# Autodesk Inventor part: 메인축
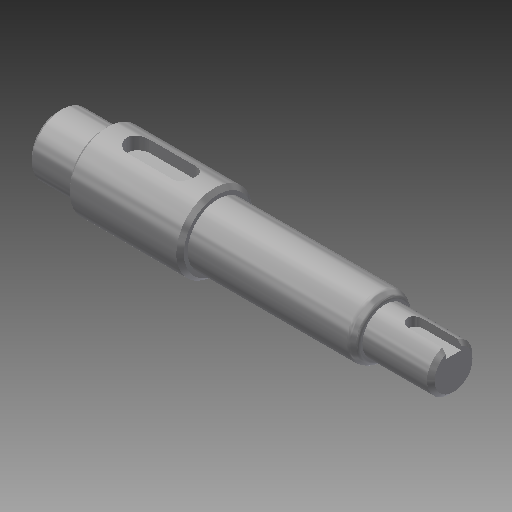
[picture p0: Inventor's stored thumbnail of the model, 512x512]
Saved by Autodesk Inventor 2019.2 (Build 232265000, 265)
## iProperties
Created: 2019-03
Part Number: 메인축
Material: 강철, 연강
Document SubType Name: Modeling
Designer: mduedu
Density: 1 g/cm^3
Appearance: 강철
Author: mduedu
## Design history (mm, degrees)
sketch "스케치1"
  geometry: L1 (0, 0)-(12, 0); L2 (12, 0)-(12, 8); L3 (12, 8)-(0, 8); L4 (0, 8)-(0, 0); L5 (12, 0)-(42, 0); L6 (42, 0)-(42, 10); L7 (42, 10)-(12, 10); L8 (12, 10)-(12, 0); L9 (42, 0)-(86, 0); L10 (86, 0)-(86, 8); L11 (86, 8)-(42, 8); L12 (42, 8)-(42, 0); L13 (86, 0)-(104, 0); L14 (104, 0)-(104, 6); L15 (104, 6)-(86, 6); L16 (86, 6)-(86, 0)
  constraints: 32 end point, 8 parallel, 4 horizontal, 4 perpendicular
  dimensions: "d0" = 16 diameter of L3 L1; "d2" = 20 diameter of L7 L5; "d3" = 16 diameter of L11 L9; "d4" = 12 diameter of L15 L13; "d5" = 12 distance of L2.end L3.end; "d6" = 30 distance of L6.end L7.end; "d7" = 86 distance between parallel lines of L10 L4; "d8" = 104 distance between parallel lines of L14 L4
revolve "회전1" sketch "스케치1" stored, may be unused: angle "d9" = 90 deg
node "작업 평면1"
sketch "스케치2" dims "d10" = 18
  geometry: L1 (6, -3)-(-6, -3); L2 (-6, -3)-(-6, 3); L3 (-6, 3)-(6, 3); L4 (6, 3)-(6, -3); L5 (15, 10)-(15, -10) reference; 3 further points
  constraints: 8 end point, 2 midpoint, 2 parallel, 2 vertical alignment, 1 horizontal, 1 horizontal alignment, 1 perpendicular, 4 other
  dimensions: "d12" = 6 distance between parallel lines of L3 L1; "d13" = 6 dimension on L5
extrude "돌출1" cut sketch "스케치2" distance "d14" = 3.5; taper "d15" = 0 deg
node "작업 평면2"
sketch "스케치3"
  geometry: L1 (-9, 6)-(-9, -6) reference; L2 (1, -2)-(-9, -2); L3 (1, 2)-(-9, 2); A1 r 2 centre (1, 0) between (1, -2) and (1, 2); 2 further points
  constraints: 4 end point, 2 point on circle, 2 point on line, 2 tangent, 1 centre point, 1 horizontal alignment, 1 midpoint, 1 parallel, 1 perpendicular
  dimensions: "d16" = 12 dimension on A1 L1; "d17" = 4 distance between parallel lines of L3 L2
extrude "돌출2" cut sketch "스케치3" distance "d18" = 2.5; taper "d19" = 0 deg
chamfer "모따기1" distance "d20" = 1; stored, may be unused: second distance "d21" = 2, angle "d22" = 45 deg
chamfer "모따기2" distance "d23" = 1; stored, may be unused: second distance "d24" = 2, angle "d25" = 45 deg
chamfer "모따기3" distance "d26" = 1.73; stored, may be unused: second distance "d27" = 2, angle "d28" = 30 deg
fillet "모깎기2" dims "d31" = 1, "d32" = 2
node "솔리드1"
